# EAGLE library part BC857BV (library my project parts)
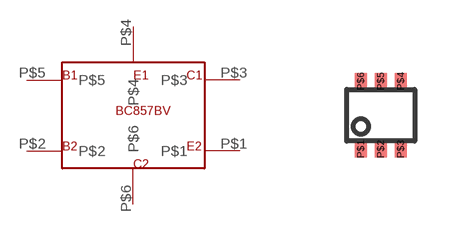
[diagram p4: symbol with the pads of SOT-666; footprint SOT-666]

Designator prefix -

## BC857BV  [SOT-666]
P$1  P$1
P$2  P$2
P$3  P$3
P$4  P$4
P$5  P$5
P$6  P$6

## Footprint SOT-666 (pad centres in mm)
smd 0.3 x 0.4: P$1 -0.5,-0.85; P$2 0,-0.85; P$3 0.5,-0.85; P$4 0.5,0.85; P$5 0,0.85; P$6 -0.5,0.85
